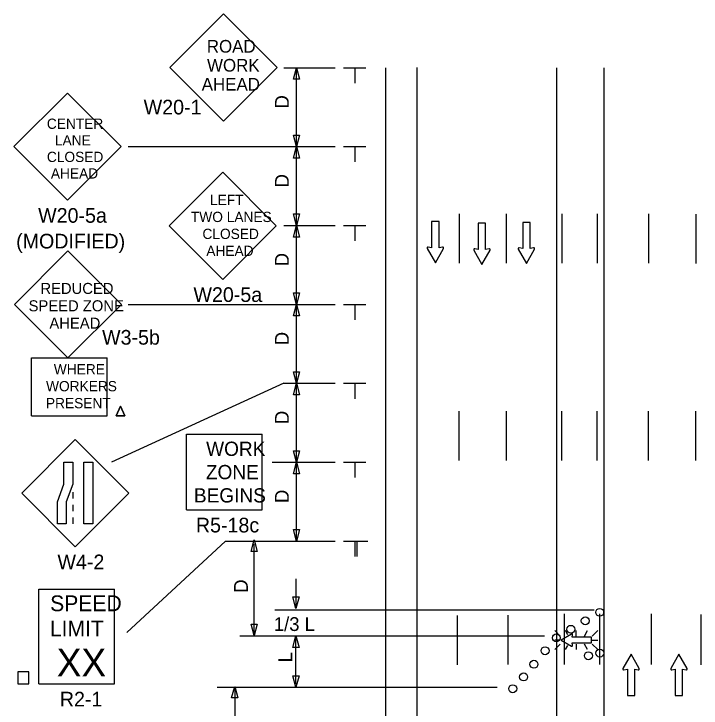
# Model space of a CAD drawing. Extents: x 20837 to 23689, y 414 to 2167.
# Drawn here: x 20925.1 to 21273.4, y 1312.5 to 1664.5 of the extents above; entities that cross this region are included whole.
import ezdxf

# ---------------------------------------------------------------- set-up
doc = ezdxf.new("R2010")
doc.units = 0
for name, color, linetype in [('ALI_LEGAL_EX', 7, 'Continuous'), ('MT_SCRATCH_LEVEL_E', 7, 'Continuous'), ('PAVT_EDGE_EX', 7, 'Continuous'), ('TRAFFIC_SIGNS_PR', 7, 'Continuous'), ('TYPICAL_EX', 7, 'Continuous'), ('TYPICAL_TEXT_DIMEN_PR', 7, 'Continuous')]:
    doc.layers.add(name, color=color, linetype=linetype)

msp = doc.modelspace()

# ---------------------------------------------------------------- linework, layer by layer
at = {"layer": 'ALI_LEGAL_EX'}
for points in [[(21150.97, 1538.09), (21150.97, 1563.09)], [(21174.75, 1538.09), (21174.75, 1563.09)], [(21202.97, 1538.09), (21202.97, 1563.09)], [(21220.87, 1538.09), (21220.87, 1563.09)], [(21246.97, 1538.09), (21246.97, 1563.09)], [(21270.97, 1537.88), (21270.97, 1562.88)], [(21150.75, 1438.1), (21150.75, 1463.1)], [(21174.75, 1438.1), (21174.75, 1463.1)], [(21202.75, 1438.1), (21202.75, 1463.1)], [(21220.65, 1438.1), (21220.65, 1463.1)], [(21246.75, 1438.1), (21246.75, 1463.1)], [(21270.75, 1438.1), (21270.75, 1463.1)], [(21149.95, 1334.41), (21149.95, 1359.42)], [(21175.6, 1334.71), (21175.6, 1359.72)], [(21204.24, 1334.7), (21204.24, 1360.39)], [(21222.15, 1334.7), (21222.15, 1360.39)], [(21248.24, 1334.7), (21248.24, 1360.39)], [(21273.43, 1334.46), (21273.43, 1359.98)]]:
    msp.add_lwpolyline(points, dxfattribs=at)
at = {"layer": 'MT_SCRATCH_LEVEL_E'}
for p, q in [((21140.57, 1559.19), (21136.82, 1559.19)), ((21136.82, 1559.19), (21136.82, 1545.93)), ((21140.57, 1559.19), (21136.82, 1559.19)), ((21136.82, 1559.19), (21136.82, 1545.93)), ((21140.57, 1545.93), (21140.57, 1559.19)), ((21140.57, 1545.93), (21140.57, 1559.19)), ((21164.2, 1558.36), (21160.46, 1558.36)), ((21160.46, 1558.36), (21160.46, 1545.11)), ((21164.2, 1558.36), (21160.46, 1558.36)), ((21160.46, 1558.36), (21160.46, 1545.11)), ((21164.2, 1545.11), (21164.2, 1558.36)), ((21164.2, 1545.11), (21164.2, 1558.36)), ((21186.73, 1558.78), (21182.99, 1558.78)), ((21182.99, 1558.78), (21182.99, 1545.52)), ((21186.73, 1558.78), (21182.99, 1558.78)), ((21182.99, 1558.78), (21182.99, 1545.52)), ((21186.73, 1545.52), (21186.73, 1558.78)), ((21186.73, 1545.52), (21186.73, 1558.78)), ((21134.57, 1545.56), (21138.71, 1538.32)), ((21134.57, 1545.56), (21138.71, 1538.32)), ((21136.82, 1545.93), (21135.05, 1546.25)), ((21136.82, 1545.93), (21135.05, 1546.25)), ((21138.71, 1538.32), (21142.83, 1545.56)), ((21138.71, 1538.32), (21142.83, 1545.56)), ((21142.34, 1546.25), (21140.57, 1545.93)), ((21142.34, 1546.25), (21140.57, 1545.93)), ((21160.46, 1545.11), (21158.68, 1545.42)), ((21160.46, 1545.11), (21158.68, 1545.42)), ((21165.98, 1545.42), (21164.2, 1545.11)), ((21165.98, 1545.42), (21164.2, 1545.11)), ((21180.73, 1545.15), (21184.88, 1537.91)), ((21180.73, 1545.15), (21184.88, 1537.91)), ((21182.99, 1545.52), (21181.21, 1545.83)), ((21182.99, 1545.52), (21181.21, 1545.83)), ((21184.88, 1537.91), (21188.99, 1545.15)), ((21184.88, 1537.91), (21188.99, 1545.15)), ((21188.51, 1545.83), (21186.73, 1545.52)), ((21188.51, 1545.83), (21186.73, 1545.52)), ((21158.2, 1544.74), (21162.35, 1537.5)), ((21158.2, 1544.74), (21162.35, 1537.5)), ((21162.35, 1537.5), (21166.46, 1544.74)), ((21162.35, 1537.5), (21166.46, 1544.74)), ((21237.9, 1339.82), (21233.79, 1332.58)), ((21237.9, 1339.82), (21233.79, 1332.58)), ((21242.05, 1332.58), (21237.9, 1339.82)), ((21242.05, 1332.58), (21237.9, 1339.82)), ((21262.17, 1339.82), (21258.06, 1332.58)), ((21262.17, 1339.82), (21258.06, 1332.58)), ((21266.31, 1332.58), (21262.17, 1339.82)), ((21266.31, 1332.58), (21262.17, 1339.82)), ((21234.27, 1331.89), (21236.05, 1332.21)), ((21234.27, 1331.89), (21236.05, 1332.21)), ((21236.05, 1332.21), (21236.05, 1318.95)), ((21236.05, 1332.21), (21236.05, 1318.95)), ((21239.79, 1318.95), (21239.79, 1332.21)), ((21239.79, 1332.21), (21241.57, 1331.89)), ((21239.79, 1318.95), (21239.79, 1332.21)), ((21239.79, 1332.21), (21241.57, 1331.89)), ((21258.54, 1331.89), (21260.32, 1332.21)), ((21258.54, 1331.89), (21260.32, 1332.21)), ((21260.32, 1332.21), (21260.32, 1318.95)), ((21260.32, 1332.21), (21260.32, 1318.95)), ((21264.06, 1318.95), (21264.06, 1332.21)), ((21264.06, 1332.21), (21265.84, 1331.89)), ((21264.06, 1318.95), (21264.06, 1332.21)), ((21264.06, 1332.21), (21265.84, 1331.89)), ((21236.05, 1318.95), (21239.79, 1318.95)), ((21236.05, 1318.95), (21239.79, 1318.95)), ((21260.32, 1318.95), (21264.06, 1318.95)), ((21260.32, 1318.95), (21264.06, 1318.95))]:
    msp.add_line(p, q, dxfattribs=at)
for centre, start, end in [((21134.98, 1545.79), 80.0362, 209.7731), ((21134.98, 1545.79), 80.0362, 209.7731), ((21142.42, 1545.79), 330.4248, 99.9638), ((21142.42, 1545.79), 330.4248, 99.9638), ((21158.61, 1544.96), 80.0362, 209.7731), ((21158.61, 1544.96), 80.0362, 209.7731), ((21166.05, 1544.96), 330.4248, 99.9638), ((21166.05, 1544.96), 330.4248, 99.9638), ((21181.14, 1545.37), 80.0362, 209.7731), ((21181.14, 1545.37), 80.0362, 209.7731), ((21188.58, 1545.38), 330.4248, 99.9638), ((21188.58, 1545.38), 330.4248, 99.9638), ((21234.2, 1332.35), 150.4248, 279.9638), ((21234.2, 1332.35), 150.4248, 279.9638), ((21241.64, 1332.35), 260.0362, 29.7731), ((21241.64, 1332.35), 260.0362, 29.7731), ((21258.46, 1332.35), 150.4248, 279.9638), ((21258.46, 1332.35), 150.4248, 279.9638), ((21265.9, 1332.35), 260.0362, 29.7731), ((21265.9, 1332.35), 260.0362, 29.7731)]:
    msp.add_arc(centre, 0.463, start, end, dxfattribs=at)
at = {"layer": 'PAVT_EDGE_EX'}
for p, q in [((21129.4, 1637.35), (21129.4, 813.35)), ((21200.14, 1637.05), (21200.14, 1162.94)), ((21224.14, 1637.05), (21224.14, 1153.29))]:
    msp.add_line(p, q, dxfattribs=at)
at = {"layer": 'TRAFFIC_SIGNS_PR'}
for p, q in [((21031.32, 1664.47), (21004.13, 1637.28)), ((21058.51, 1637.28), (21031.32, 1664.47)), ((21004.13, 1637.28), (21031.32, 1610.1)), ((21031.32, 1610.1), (21058.51, 1637.28)), ((20952.21, 1624.33), (20925.05, 1597.18)), ((20979.36, 1597.18), (20952.21, 1624.33)), ((20925.05, 1597.18), (20952.21, 1570.03)), ((20952.21, 1570.03), (20979.36, 1597.18)), ((21030.94, 1584.17), (21003.79, 1557.02)), ((21058.09, 1557.02), (21030.94, 1584.17)), ((21003.79, 1557.02), (21030.94, 1529.87)), ((21030.94, 1529.87), (21058.09, 1557.02)), ((20952.46, 1544.33), (20925.3, 1517.18)), ((20979.61, 1517.18), (20952.46, 1544.33)), ((20925.3, 1517.18), (20952.46, 1490.03)), ((20952.46, 1490.03), (20979.61, 1517.18)), ((20933.98, 1490.06), (20972.38, 1490.06)), ((20933.98, 1460.74), (20933.98, 1490.06)), ((20972.38, 1460.74), (20972.38, 1490.06)), ((20933.98, 1460.74), (20972.38, 1460.74)), ((21012.51, 1413.02), (21012.51, 1451.42)), ((21012.51, 1451.42), (21050.91, 1451.42)), ((21050.91, 1413.02), (21050.91, 1451.42)), ((20956.19, 1448.67), (20929.04, 1421.51)), ((20983.34, 1421.51), (20956.19, 1448.67)), ((20954.94, 1422.01), (20954.94, 1418.81)), ((20929.04, 1421.51), (20956.19, 1394.36)), ((20956.19, 1394.36), (20983.34, 1421.51)), ((20954.94, 1415.61), (20954.94, 1412.41)), ((21012.51, 1413.02), (21050.91, 1413.02)), ((20954.94, 1409.21), (20954.94, 1406.01)), ((20937.68, 1372.81), (20976.08, 1372.81)), ((20937.68, 1324.81), (20937.68, 1372.81)), ((20976.08, 1324.81), (20976.08, 1372.81)), ((21199.22, 1351.91), (21202.04, 1349.09)), ((21205.94, 1349.73), (21204.68, 1351.91)), ((21210.12, 1349.09), (21210.12, 1351.91)), ((21214.26, 1349.09), (21215.89, 1351.91)), ((21218.21, 1349.09), (21221.03, 1351.91)), ((21202.04, 1347.06), (21199.22, 1347.06)), ((21199.22, 1342.21), (21202.04, 1345.03)), ((21210.12, 1345.03), (21210.12, 1342.21)), ((21215.91, 1342.21), (21214.28, 1345.03)), ((21218.21, 1347.06), (21221.03, 1347.06)), ((21218.21, 1345.03), (21221.03, 1342.21)), ((21204.66, 1342.21), (21205.86, 1344.3)), ((20937.68, 1324.81), (20976.08, 1324.81))]:
    msp.add_line(p, q, dxfattribs=at)
for points in [[(20979.12, 1465.68), (20976.89, 1460.74)], [(20976.89, 1460.74), (20979.12, 1465.68)], [(20981.36, 1460.74), (20979.12, 1465.68)], [(20979.12, 1465.68), (20981.36, 1460.74)], [(20976.89, 1460.74), (20981.36, 1460.74)], [(20981.36, 1460.74), (20976.89, 1460.74)], [(21207.8, 1350.08), (21202.49, 1347.06), (21207.8, 1344.02)], [(21208.3, 1344.38), (21208.07, 1345.68), (21217.79, 1345.68), (21217.79, 1348.42), (21208.07, 1348.42), (21208.3, 1349.72)]]:
    msp.add_lwpolyline(points, dxfattribs=at)
for points in [[(20954.94, 1437.25), (20954.94, 1426.07), (20951.6, 1417.19), (20951.6, 1406.01), (20947.1, 1406.01), (20947.1, 1417.19), (20950.45, 1426.07), (20950.45, 1437.25)], [(20965.08, 1437.25), (20965.08, 1406.01), (20960.58, 1406.01), (20960.58, 1437.25)], [(20927.07, 1324.81), (20932.66, 1324.81), (20932.66, 1330.98), (20927.07, 1330.98)]]:
    msp.add_lwpolyline(points, close=True, dxfattribs=at)
for centre in [(21222.02, 1361.1), (21214.69, 1356.79), (21207.37, 1352.49), (21200.04, 1348.18), (21194.32, 1341.61), (21216.31, 1339.08), (21222.08, 1340.43), (21188.68, 1334.76), (21183.44, 1328.36), (21177.93, 1322.34)]:
    msp.add_circle(centre, 2, dxfattribs=at)
for centre, start, end in [((21207.96, 1349.78), 350.7308, 118.8916), ((21207.96, 1344.32), 241.4833, 9.9593)]:
    msp.add_arc(centre, 0.341, start, end, dxfattribs=at)
at = {"layer": 'TYPICAL_EX'}
msp.add_line((21113.4, 1637.05), (21113.4, 813.35), dxfattribs=at)
at = {"layer": 'TYPICAL_TEXT_DIMEN_PR'}
for p, q in [((21061.97, 1637.18), (21087.97, 1637.18)), ((21066.74, 1631.32), (21068.31, 1637.18)), ((21068.31, 1597.18), (21068.31, 1637.18)), ((21068.31, 1637.18), (21069.88, 1631.32)), ((21092.22, 1637.18), (21103.47, 1637.18)), ((21097.84, 1637.18), (21097.84, 1629.39)), ((21068.31, 1631.32), (21066.74, 1631.32)), ((21069.88, 1631.32), (21068.31, 1631.32)), ((21068.31, 1597.18), (21066.74, 1603.04)), ((21066.74, 1603.04), (21068.31, 1603.04)), ((21068.31, 1603.04), (21069.88, 1603.04)), ((21069.88, 1603.04), (21068.31, 1597.18)), ((20982.95, 1597.18), (21087.97, 1597.18)), ((21066.74, 1591.32), (21068.31, 1597.18)), ((21068.31, 1557.18), (21068.31, 1597.18)), ((21068.31, 1597.18), (21069.88, 1591.32)), ((21092.22, 1597.18), (21103.47, 1597.18)), ((21097.84, 1597.18), (21097.84, 1589.39)), ((21068.31, 1591.32), (21066.74, 1591.32)), ((21069.88, 1591.32), (21068.31, 1591.32)), ((21068.31, 1557.18), (21066.74, 1563.04)), ((21066.74, 1563.04), (21068.31, 1563.04)), ((21068.31, 1563.04), (21069.88, 1563.04)), ((21069.88, 1563.04), (21068.31, 1557.18)), ((21061.97, 1557.18), (21087.97, 1557.18)), ((21066.74, 1551.32), (21068.31, 1557.18)), ((21068.31, 1517.18), (21068.31, 1557.18)), ((21068.31, 1557.18), (21069.88, 1551.32)), ((21092.22, 1557.18), (21103.47, 1557.18)), ((21097.84, 1557.18), (21097.84, 1549.39)), ((21068.31, 1551.32), (21066.74, 1551.32)), ((21069.88, 1551.32), (21068.31, 1551.32)), ((21068.31, 1517.18), (21066.74, 1523.04)), ((21066.74, 1523.04), (21068.31, 1523.04)), ((21068.31, 1523.04), (21069.88, 1523.04)), ((21069.88, 1523.04), (21068.31, 1517.18)), ((20982.95, 1517.18), (21087.97, 1517.18)), ((21066.74, 1511.32), (21068.31, 1517.18)), ((21068.31, 1477.18), (21068.31, 1517.18)), ((21068.31, 1517.18), (21069.88, 1511.32)), ((21092.22, 1517.18), (21103.47, 1517.18)), ((21097.84, 1517.18), (21097.84, 1509.39)), ((21068.31, 1511.32), (21066.74, 1511.32)), ((21069.88, 1511.32), (21068.31, 1511.32)), ((21068.31, 1477.18), (21066.74, 1483.04)), ((21066.74, 1483.04), (21068.31, 1483.04)), ((21068.31, 1483.04), (21069.88, 1483.04)), ((21069.88, 1483.04), (21068.31, 1477.18)), ((21061.97, 1477.18), (20974.6, 1437.3)), ((21061.97, 1477.18), (21087.97, 1477.18)), ((21066.74, 1471.32), (21068.31, 1477.18)), ((21068.31, 1437.18), (21068.31, 1477.18)), ((21068.31, 1477.18), (21069.88, 1471.32)), ((21092.22, 1477.18), (21103.47, 1477.18)), ((21097.84, 1477.18), (21097.84, 1469.39)), ((21068.31, 1471.32), (21066.74, 1471.32)), ((21069.88, 1471.32), (21068.31, 1471.32)), ((21068.31, 1437.18), (21066.74, 1443.04)), ((21066.74, 1443.04), (21068.31, 1443.04)), ((21068.31, 1443.04), (21069.88, 1443.04)), ((21069.88, 1443.04), (21068.31, 1437.18)), ((21055.96, 1437.18), (21087.97, 1437.18)), ((21066.74, 1431.32), (21068.31, 1437.18)), ((21068.31, 1397.18), (21068.31, 1437.18)), ((21068.31, 1437.18), (21069.88, 1431.32)), ((21092.22, 1437.18), (21103.47, 1437.18)), ((21097.84, 1437.18), (21097.84, 1429.39)), ((21068.31, 1431.32), (21066.74, 1431.32)), ((21069.88, 1431.32), (21068.31, 1431.32)), ((21068.31, 1397.18), (21066.74, 1403.04)), ((21066.74, 1403.04), (21068.31, 1403.04)), ((21068.31, 1403.04), (21069.88, 1403.04)), ((21069.88, 1403.04), (21068.31, 1397.18)), ((21045.26, 1391.89), (21046.83, 1397.76)), ((21046.83, 1397.76), (21048.4, 1391.89)), ((21032.25, 1397.18), (20982.27, 1350.81)), ((21032.25, 1397.18), (21086.52, 1397.18)), ((21032.25, 1397.18), (21087.97, 1397.18)), ((21046.82, 1349.4), (21046.82, 1395.74)), ((21092.22, 1397.18), (21103.47, 1397.18)), ((21093.29, 1397.18), (21104.54, 1397.18)), ((21097.84, 1397.18), (21097.84, 1389.39)), ((21098.91, 1397.18), (21098.91, 1389.39)), ((21046.83, 1391.89), (21045.26, 1391.89)), ((21048.4, 1391.89), (21046.83, 1391.89)), ((21068.04, 1378.03), (21068.04, 1363.11)), ((21068.04, 1363.11), (21066.47, 1368.97)), ((21066.47, 1368.97), (21068.04, 1368.97)), ((21068.04, 1368.97), (21069.61, 1368.97)), ((21069.61, 1368.97), (21068.04, 1363.11)), ((21057.29, 1362.34), (21219.19, 1362.34)), ((21046.83, 1349.29), (21045.26, 1355.15)), ((21045.26, 1355.15), (21046.83, 1355.15)), ((21046.83, 1355.15), (21048.4, 1355.15)), ((21048.4, 1355.15), (21046.83, 1349.29)), ((21039.66, 1349.1), (21194.1, 1349.1)), ((21066.47, 1343.28), (21068.04, 1349.14)), ((21068.04, 1349.14), (21069.61, 1343.28)), ((21068.04, 1324.61), (21068.04, 1348.72)), ((21068.04, 1343.28), (21066.47, 1343.28)), ((21069.61, 1343.28), (21068.04, 1343.28)), ((21068.04, 1323.1), (21066.47, 1328.96)), ((21066.47, 1328.96), (21068.04, 1328.96)), ((21068.04, 1328.96), (21069.61, 1328.96)), ((21069.61, 1328.96), (21068.04, 1323.1)), ((21035.42, 1317.69), (21036.99, 1323.55)), ((21036.99, 1323.55), (21038.56, 1317.69)), ((21037, 1323.28), (21037, 1266.41)), ((21028.1, 1323.23), (21170.08, 1323.23)), ((21036.99, 1317.69), (21035.42, 1317.69)), ((21038.56, 1317.69), (21036.99, 1317.69))]:
    msp.add_line(p, q, dxfattribs=at)

# ---------------------------------------------------------------- texts
at = {"layer": 'TRAFFIC_SIGNS_PR'}
for s, height, p in [('ROAD', 6.408, (21022.85, 1644.83)), ('WORK', 6.408, (21022.96, 1635.21)), ('AHEAD', 6.408, (21020.27, 1625.6)), ('W20-1', 7.449, (20990.83, 1613.49)), ('CENTER', 5.2, (20941.78, 1606.18)), ('LANE', 5.2, (20945.86, 1597.78)), ('CLOSED', 5.2, (20941.79, 1589.38)), ('AHEAD', 5.2, (20943.81, 1580.98)), ('LEFT', 5.2, (21024.48, 1567.55)), ('W20-5a', 7.44, (20937.35, 1558.59)), ('TWO LANES', 5.2, (21014.8, 1558.95)), ('CLOSED', 5.2, (21020.65, 1550.35)), ('(MODIFIED)', 7.44, (20926.2, 1545.55)), ('AHEAD', 5.2, (21022.6, 1541.75)), ('REDUCED', 5.6, (20938.51, 1522.49)), ('W20-5a', 7.44, (21016.08, 1518.43)), ('SPEED ZONE', 5.6, (20932.51, 1513.69)), ('AHEAD', 5.6, (20943.07, 1504.89)), ('W3-5b', 7.44, (20969.76, 1496.79)), ('WHERE', 5.2, (20945.29, 1481.75)), ('WORKERS', 5.2, (20941.36, 1473.15)), ('PRESENT', 5.2, (20941.29, 1464.55)), ('WORK', 7.217, (21022.51, 1440.39)), ('ZONE', 7.217, (21022.39, 1428.58)), ('BEGINS', 7.217, (21016.32, 1416.77)), ('R5-18c', 7.44, (21017.32, 1401.58)), ('W4-2', 7.44, (20947.15, 1382.92)), ('SPEED', 8, (20943.44, 1361.67)), ('LIMIT', 8, (20943.28, 1348.87)), ('XX', 14.031, (20946.79, 1328.57)), ('R2-1', 7.44, (20948.35, 1313.37))]:
    msp.add_text(s, height=height, dxfattribs=at).set_placement(p)
at = {"layer": 'TYPICAL_TEXT_DIMEN_PR'}
for s, p in [('D', (21064.41, 1616.5)), ('D', (21064.41, 1576.5)), ('D', (21064.41, 1536.5)), ('D', (21064.41, 1496.5)), ('D', (21064.41, 1456.5)), ('D', (21064.41, 1416.5)), ('D', (21043.66, 1371.02)), ('L', (21066.19, 1335.72))]:
    msp.add_text(s, height=7, rotation=90, dxfattribs=at).set_placement(p)
msp.add_text('1/3 L', height=7, dxfattribs=at).set_placement((21056.82, 1351.63))

doc.saveas('drawing.dxf')
